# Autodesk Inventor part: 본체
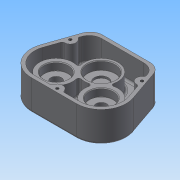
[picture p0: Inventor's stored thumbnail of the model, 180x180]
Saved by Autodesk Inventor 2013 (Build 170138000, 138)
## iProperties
Created: 2014-12
Part Number: 본체
Material: 일반
Document SubType Name: Modeling
Designer: Administrator
Density: 1 g/cm^3
Author: Administrator
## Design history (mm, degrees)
sketch "스케치1"
  geometry: L1 (0, 0)-(-32.527, -32.527); L2 (0, 0)-(32.527, -32.527); L3 (0, 0)-(0, -46); L4 (-47, 36)-(47, 36); L5 (-32.527, -68.527)-(32.527, -68.527); L6 (47, 36)-(66.565, -20.803); L7 (-47, 36)-(-66.565, -20.803); A1 r 46 centre (0, 0) between (-32.527, -32.527) and (32.527, -32.527); A2 r 36 centre (32.527, -32.527) between (32.527, -68.527) and (66.565, -20.803); A3 r 36 centre (-32.527, -32.527) between (-66.565, -20.803) and (-32.527, -68.527); 2 further points
  constraints: 14 end point, 7 point on circle, 3 centre point, 3 coincident, 3 tangent, 1 midpoint, 1 parallel, 1 perpendicular, 1 vertical, 1 vertical alignment
  dimensions: "d2" = 92 diameter of A1; "d3" = 90 deg angle of L2 L1; "d5" = 45 deg angle of L3 L1; "d9" = 94 distance of L4.start L4.end; "d10" = 36 distance from line of L4 point (0, 0)
extrude "돌출1" new body sketch "스케치1" distance "d11" = 44; taper "d12" = 0 deg
fillet "모깎기1" dims "d13" = 18
fillet "모깎기3" dims "d15" = 3
sketch "스케치27"
  geometry: L1 (-66.565, -20.803)-(-51.181, 23.862) reference; L2 (51.181, 23.862)-(66.565, -20.803) reference; L3 (-34.162, 36)-(34.162, 36) reference; L4 (-43.434, 31)-(-61.837, -22.432); L5 (43.434, 31)-(61.837, -22.432); L6 (-32.527, -63.527)-(32.527, -63.527); L7 (-43.434, 31)-(43.434, 31); L8 (-34.162, 36)-(34.162, 36) reference; L9 (51.181, 23.862)-(66.565, -20.803) reference; L10 (32.527, -68.527)-(-32.527, -68.527) reference; L11 (-66.565, -20.803)-(-51.181, 23.862) reference; A1 r 36 centre (-32.527, -32.527) between (-66.565, -20.803) and (-32.527, -68.527) reference; A2 r 36 centre (32.527, -32.527) between (32.527, -68.527) and (66.565, -20.803) reference; A3 r 31 centre (32.527, -32.527) between (32.527, -63.527) and (61.837, -22.432); A4 r 31 centre (-32.527, -32.527) between (-61.837, -22.432) and (-32.527, -63.527); A5 r 18 centre (-34.162, 18) between (-34.162, 36) and (-51.181, 23.862) reference; A6 r 18 centre (34.162, 18) between (51.181, 23.862) and (34.162, 36) reference; A7 r 36 centre (32.527, -32.527) between (32.527, -68.527) and (66.565, -20.803) reference; A8 r 36 centre (-32.527, -32.527) between (-66.565, -20.803) and (-32.527, -68.527) reference; 3 further points
  constraints: 8 end point, 4 point on circle, 4 tangent, 3 coincident, 2 centre point, 2 parallel, 1 midpoint, 1 vertical alignment
  dimensions: "d88" = 62 diameter of A3; "d90" = 62 diameter of A4; "d93" = 5 distance from line of L1 L4.start; "d94" = 5 distance from line of L3 point (0, 31); "d95" = 43.43386 distance of L5.start point (0, 31)
extrude "돌출17" cut sketch "스케치27" distance "d96" = 34; taper "d97" = 0 deg
fillet "모깎기5" dims "d98" = 18
sketch "스케치35"
  geometry: L1 (-61.837, -22.432)-(-47.615, 18.862) reference; L2 (-34.162, 36)-(34.162, 36) reference; A1 r 8 centre (-51.7, 7) between (-54.305, -0.564) and (-49.095, 14.564); 1 further point
  constraints: 3 point on line, 2 point on circle, 1 centre point
  dimensions: "d114" = 16 diameter of A1; "d115" = 29 distance from line of L2 A1.centre
extrude "돌출23" join sketch "스케치35" stored distance "d116" = 3; taper "d117" = 0 deg
sketch "스케치36"
  geometry: L1 (32.527, -63.527)-(-32.527, -63.527) reference; A1 r 8 centre (0, -63.527) between (8, -63.527) and (-8, -63.527); 1 further point
  constraints: 2 point on circle, 2 point on line, 1 centre point, 1 midpoint
  dimensions: "d118" = 16 diameter of A1
extrude "돌출24" join sketch "스케치36" stored distance "d119" = 3; taper "d120" = 0 deg
hole "구멍3" diameter "d123" = 4.134; stored, may be unused: countersink angle "d127" = 90 deg, drill point angle "d129" = 118 deg; dims "d121" = 10, "d122" = 10, "d124" = 20, "d125" = 4, "d126" = 2, "d128" = 23
hole "구멍4" diameter "d132" = 4.134; stored, may be unused: countersink angle "d136" = 90 deg, drill point angle "d138" = 118 deg; dims "d130" = 10, "d131" = 10, "d133" = 20, "d134" = 4, "d135" = 2, "d137" = 23
sketch "스케치37"
  geometry: C1 r 20 at (-32.527, -32.527); A1 r 33 centre (-32.527, -32.527) between (-63.728, -21.78) and (-32.527, -65.527) reference; 1 further point
  constraints: 1 centre point, 1 coincident
  dimensions: "d139" = 40 diameter of C1
extrude "돌출25" join sketch "스케치37" distance "d140" = 7; taper "d141" = -10 deg
sketch "스케치38"
  geometry: C1 r 18.766 at (0, 0) reference; C2 r 15 at (0, 0); 1 further point
  constraints: 1 centre point, 1 coincident
  dimensions: "d142" = 30 diameter of C2
extrude "돌출26" cut sketch "스케치38" distance "d143" = 7; taper "d144" = 0 deg
sketch "스케치39"
  geometry: C1 r 15 at (0, 0) reference; C2 r 7.75 at (0, 0); 1 further point
  constraints: 1 centre point, 1 coincident
  dimensions: "d145" = 15.5 diameter of C2
extrude "돌출27" cut sketch "스케치39" distance "d146" = 10; taper "d147" = 0 deg
sketch "스케치40"
  geometry: C1 r 7.75 at (32.527, -32.527) reference; C2 r 24 at (32.527, -32.527); A1 r 31 centre (32.527, -32.527) between (32.527, -63.527) and (61.837, -22.432) reference; 1 further point
  constraints: 1 centre point, 1 coincident
  dimensions: "d148" = 48 diameter of C2
extrude "돌출28" join sketch "스케치40" distance "d149" = 23; taper "d150" = 0 deg
sketch "스케치41"
  geometry: C1 r 7.75 at (0, 0) reference; C2 r 24 at (0, 0) reference; C3 r 17.5 at (0, 0); 1 further point
  constraints: 1 centre point, 1 coincident
  dimensions: "d151" = 35 diameter of C3
extrude "돌출29" cut sketch "스케치41" distance "d152" = 11; taper "d153" = 0 deg
sketch "스케치42"
  geometry: C1 r 24 at (0, 0); 1 further point
  constraints: 1 centre point, 1 coincident
  dimensions: "d154" = 48 diameter of C1
extrude "돌출30" join sketch "스케치42" distance "d155" = 23; taper "d156" = 0 deg
sketch "스케치43"
  geometry: C1 r 20 at (0, 0); A1 r 24 centre (0, 0) between (21.111, -11.416) and (11.416, -21.111) reference
  constraints: 1 centre point, 1 coincident
  dimensions: "d157" = 40 diameter of C1
extrude "돌출31" cut sketch "스케치43" distance "d158" = 12; taper "d159" = 0 deg
sketch "스케치44"
  geometry: C1 r 20 at (0, 0) reference; C2 r 10 at (0, 0)
  constraints: 1 centre point, 1 coincident
  dimensions: "d160" = 20 diameter of C2
extrude "돌출32" cut sketch "스케치44" distance "d161" = 3; taper "d162" = 0 deg
sketch "스케치45"
  geometry: C1 r 24 at (-32.527, -32.527); A1 r 31 centre (-32.527, -32.527) between (-61.837, -22.432) and (-32.527, -63.527) reference
  constraints: 1 centre point, 1 coincident
  dimensions: "d163" = 48 diameter of C1
extrude "돌출33" join sketch "스케치45" distance "d164" = 23; taper "d165" = 0 deg
sketch "스케치46"
  geometry: C1 r 17.5 at (-32.527, -32.527); A1 r 24 centre (-32.527, -32.527) between (-21.111, -11.416) and (-11.416, -21.111) reference
  constraints: 1 centre point, 1 coincident
  dimensions: "d166" = 35 diameter of C1
extrude "돌출34" cut sketch "스케치46" distance "d167" = 11; taper "d168" = 0 deg
sketch "스케치47"
  geometry: C1 r 20 at (32.527, -32.527); A1 r 33 centre (32.527, -32.527) between (32.527, -65.527) and (63.728, -21.78) reference; 1 further point
  constraints: 1 centre point, 1 coincident
  dimensions: "d169" = 40 diameter of C1
extrude "돌출35" join sketch "스케치47" distance "d170" = 7; taper "d171" = -10 deg
sketch "스케치48"
  geometry: C1 r 18.766 at (0, 0) reference; C2 r 15 at (0, 0); 1 further point
  constraints: 1 centre point, 1 coincident
  dimensions: "d172" = 30 diameter of C2
extrude "돌출36" cut sketch "스케치48" distance "d173" = 7; taper "d174" = 0 deg
sketch "스케치49"
  geometry: C1 r 15 at (0, 0) reference; C2 r 7.75 at (0, 0); 1 further point
  constraints: 1 centre point, 1 coincident
  dimensions: "d175" = 15.5 diameter of C2
extrude "돌출37" cut sketch "스케치49" stored distance "d176" = 10; taper "d177" = 0 deg
fillet "모깎기6" dims "d178" = 3
fillet "모깎기7" dims "d179" = 3
fillet "모깎기8" dims "d180" = 3
fillet "모깎기9" dims "d181" = 3
fillet "모깎기10" dims "d182" = 3
chamfer "모따기1" distance "d183" = 1; stored, may be unused: second distance "d184" = 2, angle "d185" = 45 deg
fillet "모깎기11" dims "d186" = 0.3
fillet "모깎기12" dims "d187" = 0.1
chamfer "모따기2" distance "d188" = 1; stored, may be unused: second distance "d189" = 2, angle "d190" = 45 deg
node "솔리드1"
mirror "대칭3"
node "절단 모서리 투영5"
other parameters: "d7" = 72, "d8" = 72
